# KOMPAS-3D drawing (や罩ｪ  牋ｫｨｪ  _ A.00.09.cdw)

Views: Спереди 1, Спереди, Проекционный вид 2, Изометрия XYZ 3, Изометрия XYZ, Разрез А-А
Referenced files in C:\Users\s.slezkin\Desktop\Раскатчик арок 2\: Втулка ролика _ A.00.09.m3d, Втулка ролика _ A.00.09.cdw
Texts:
  Втулка ролика
  http://vk.com/sergey_krd
  Сталь 20  ГОСТ 1050-88
Dimensions and other numbers on the sheet: 72; 1; 8; 15; 20; 1:1; 0,17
